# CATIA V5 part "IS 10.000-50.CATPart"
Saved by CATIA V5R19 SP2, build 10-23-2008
Part number: IS 10.000-50
Bounding box of the stored display mesh (mm): x -97.324 to 97.324, y -97.5 to 97.5, z 0 to 260
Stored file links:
  C:\Users\Bora\Desktop\3D Katı model\IS serisi\IS 10.000\IS 10.000-50.CATPart
  C:\Program Files\Dassault Systemes\B19\intel_a\reffiles\standard\MetricThickPitch.txt
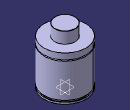
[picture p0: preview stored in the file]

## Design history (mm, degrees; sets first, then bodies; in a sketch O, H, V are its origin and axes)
Body1 (main body)
  Sketch1 on yz-plane, origin (0, 0, 0), H (0, 1, 0), V (0, 0, 1)
    point P1 (97.5, 179)
    point P4 (97.5, 174)
    point P7 (47.5, 259)
    point P9 (47.5, 259)
    point P13 (97.5, 179)
    point P14 (97.5, 174)
    line L1 (97.5, 179) -> (97.5, 207)
    line L2 (97.5, 16) -> (97.5, 174)
    line L3 (93.5, 16) -> (93.5, 8)
    arc A1 centre (46.5, 259) radius 1 from (47.5, 259) to (46.5, 260) ccw
    line L4 (47.5, 259) -> (47.5, 207)
    line L5 (97.5, 0) -> (97.5, 8)
    arc A2 centre (97.5, 176.5) radius 2.5 from (97.5, 179) to (97.5, 174) ccw
    line L6 (46.5, 260) -> (0, 260)
    point P15 (0, 260)
    line L7 (47.5, 207) -> (97.5, 207)
    line L8 (93.5, 16) -> (97.5, 16)
    line L9 (93.5, 8) -> (97.5, 8)
    line L10 (97.5, 0) -> (0, 0)
    tangency: L6 A1
    coincidence: P15 V, P1 P13, P4 P14, P7 P9
    horizontal: L7 H, L8 H, L9 H, L10 H
  Shaft1: profile Sketch1, axis Sketch1.V, angle 360
  Sketch2 on face of Shaft1 from Sketch1.L10, origin (0, 0, 0), H (1, 0, 0), V (0, -1, 0)
    point P1 (60, 0)
    distance P1 V = 60
  Hole1: placed by Sketch2, at (60, 0, 0) direction (0, 0, 1), diameter 10.106, depth 16, threaded "M12", thread diameter 12, thread depth 16, pitch 1.75
  CircPattern1: of Hole1, instances 4, angular step 90, axis from xy-plane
